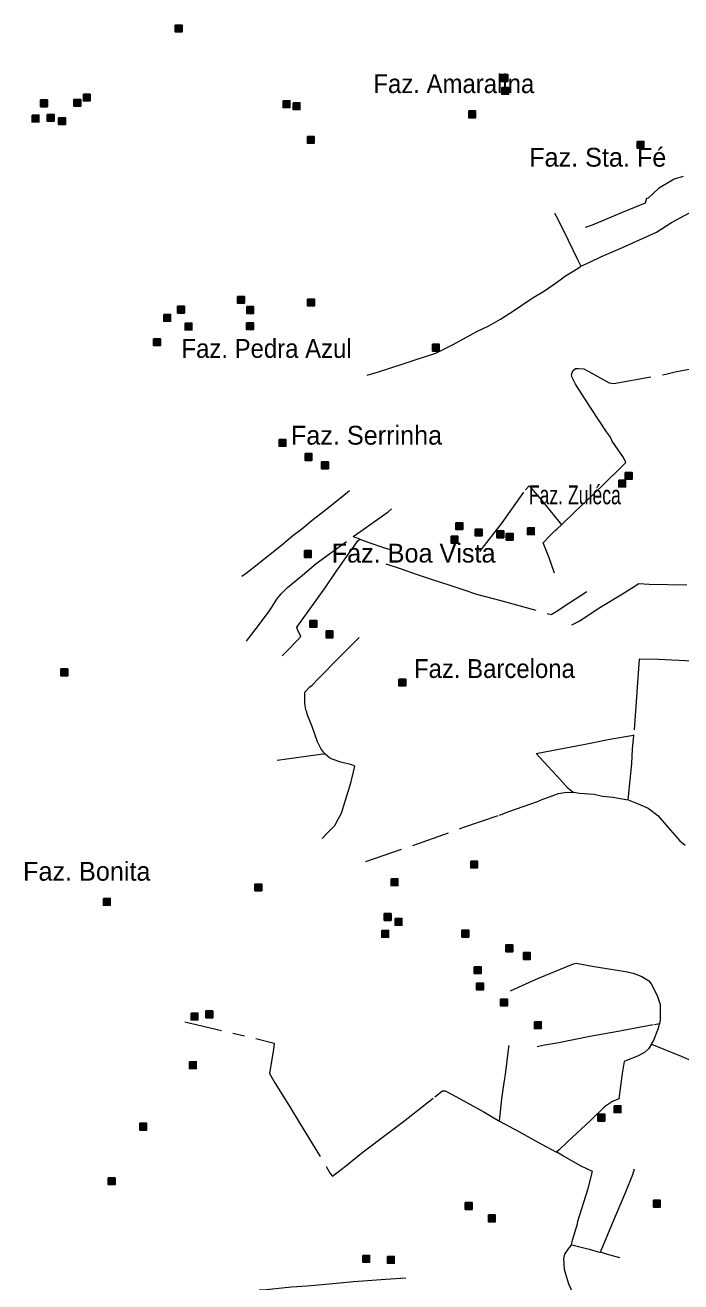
# Model space of a CAD drawing. Extents: x 393.5 to 446.9, y 8064.8 to 8120.4.
# Drawn here: x 399.42 to 404.99, y 8098.67 to 8109.36 of the extents above; entities that cross this region are included whole.
import ezdxf

# ---------------------------------------------------------------- set-up
doc = ezdxf.new("R2010")
doc.units = 0
doc.header["$LTSCALE"] = 0.064
doc.linetypes.add('DOT_DASHED', pattern=[7.7, 5, -1.2, 0.3, -1.2])
doc.layers.add('2', color=7, linetype='Continuous', lineweight=25)
doc.layers.add('22', color=7, linetype='DOT_DASHED', lineweight=13)
doc.layers.add('61', color=7, linetype='Continuous')

msp = doc.modelspace()

# ---------------------------------------------------------------- hatches: boundary and pattern name
at = {"layer": '2'}
for points in [[(400.692, 8109.3558), (400.75, 8109.3558), (400.75, 8109.2978), (400.692, 8109.2978)], [(403.4613, 8108.9358), (403.5193, 8108.9358), (403.5193, 8108.8778), (403.4613, 8108.8778)], [(399.9114, 8108.7688), (399.9694, 8108.7688), (399.9694, 8108.7108), (399.9114, 8108.7108)], [(403.4666, 8108.8256), (403.5246, 8108.8256), (403.5246, 8108.7676), (403.4666, 8108.7676)], [(399.5481, 8108.7203), (399.6061, 8108.7203), (399.6061, 8108.6623), (399.5481, 8108.6623)], [(399.832, 8108.7241), (399.89, 8108.7241), (399.89, 8108.6661), (399.832, 8108.6661)], [(401.6092, 8108.7122), (401.6672, 8108.7122), (401.6672, 8108.6542), (401.6092, 8108.6542)], [(401.6943, 8108.6962), (401.7523, 8108.6962), (401.7523, 8108.6382), (401.6943, 8108.6382)], [(403.1868, 8108.6266), (403.2448, 8108.6266), (403.2448, 8108.5686), (403.1868, 8108.5686)], [(399.4754, 8108.591), (399.5334, 8108.591), (399.5334, 8108.533), (399.4754, 8108.533)], [(399.6053, 8108.5969), (399.6633, 8108.5969), (399.6633, 8108.5389), (399.6053, 8108.5389)], [(399.7012, 8108.5686), (399.7592, 8108.5686), (399.7592, 8108.5106), (399.7012, 8108.5106)], [(401.8147, 8108.4095), (401.8727, 8108.4095), (401.8727, 8108.3515), (401.8147, 8108.3515)], [(404.6172, 8108.3674), (404.6752, 8108.3674), (404.6752, 8108.3094), (404.6172, 8108.3094)], [(401.2219, 8107.0492), (401.2799, 8107.0492), (401.2799, 8106.9912), (401.2219, 8106.9912)], [(401.8169, 8107.0259), (401.8749, 8107.0259), (401.8749, 8106.9679), (401.8169, 8106.9679)], [(400.712, 8106.9658), (400.77, 8106.9658), (400.77, 8106.9078), (400.712, 8106.9078)], [(401.2995, 8106.9627), (401.3575, 8106.9627), (401.3575, 8106.9047), (401.2995, 8106.9047)], [(400.5945, 8106.8956), (400.6525, 8106.8956), (400.6525, 8106.8376), (400.5945, 8106.8376)], [(400.7756, 8106.8219), (400.8336, 8106.8219), (400.8336, 8106.7639), (400.7756, 8106.7639)], [(401.2982, 8106.8258), (401.3562, 8106.8258), (401.3562, 8106.7678), (401.2982, 8106.7678)], [(400.5087, 8106.6894), (400.5667, 8106.6894), (400.5667, 8106.6314), (400.5087, 8106.6314)], [(402.8782, 8106.6418), (402.9362, 8106.6418), (402.9362, 8106.5838), (402.8782, 8106.5838)], [(401.5744, 8105.8325), (401.6324, 8105.8325), (401.6324, 8105.7745), (401.5744, 8105.7745)], [(401.7956, 8105.7133), (401.8536, 8105.7133), (401.8536, 8105.6553), (401.7956, 8105.6553)], [(401.9352, 8105.6414), (401.9932, 8105.6414), (401.9932, 8105.5834), (401.9352, 8105.5834)], [(404.5165, 8105.5526), (404.5745, 8105.5526), (404.5745, 8105.4946), (404.5165, 8105.4946)], [(404.4601, 8105.4881), (404.5181, 8105.4881), (404.5181, 8105.4301), (404.4601, 8105.4301)], [(403.0767, 8105.125), (403.1347, 8105.125), (403.1347, 8105.067), (403.0767, 8105.067)], [(403.0365, 8105.0101), (403.0945, 8105.0101), (403.0945, 8104.9521), (403.0365, 8104.9521)], [(403.2421, 8105.071), (403.3001, 8105.071), (403.3001, 8105.013), (403.2421, 8105.013)], [(403.4251, 8105.0555), (403.4831, 8105.0555), (403.4831, 8104.9975), (403.4251, 8104.9975)], [(403.5051, 8105.0347), (403.5631, 8105.0347), (403.5631, 8104.9767), (403.5051, 8104.9767)], [(403.6853, 8105.0819), (403.7433, 8105.0819), (403.7433, 8105.0239), (403.6853, 8105.0239)], [(401.7897, 8104.8878), (401.8477, 8104.8878), (401.8477, 8104.8298), (401.7897, 8104.8298)], [(401.8366, 8104.2946), (401.8946, 8104.2946), (401.8946, 8104.2366), (401.8366, 8104.2366)], [(401.9734, 8104.2048), (402.0314, 8104.2048), (402.0314, 8104.1468), (401.9734, 8104.1468)], [(399.7212, 8103.8813), (399.7792, 8103.8813), (399.7792, 8103.8233), (399.7212, 8103.8233)], [(402.5931, 8103.796), (402.6511, 8103.796), (402.6511, 8103.738), (402.5931, 8103.738)], [(403.2025, 8102.2483), (403.2605, 8102.2483), (403.2605, 8102.1903), (403.2025, 8102.1903)], [(401.3688, 8102.0531), (401.4268, 8102.0531), (401.4268, 8101.9951), (401.3688, 8101.9951)], [(402.5265, 8102.0984), (402.5845, 8102.0984), (402.5845, 8102.0404), (402.5265, 8102.0404)], [(400.0826, 8101.9302), (400.1406, 8101.9302), (400.1406, 8101.8722), (400.0826, 8101.8722)], [(402.4677, 8101.8018), (402.5257, 8101.8018), (402.5257, 8101.7438), (402.4677, 8101.7438)], [(402.5606, 8101.7609), (402.6186, 8101.7609), (402.6186, 8101.7029), (402.5606, 8101.7029)], [(402.4471, 8101.659), (402.5051, 8101.659), (402.5051, 8101.601), (402.4471, 8101.601)], [(403.1282, 8101.6599), (403.1862, 8101.6599), (403.1862, 8101.6019), (403.1282, 8101.6019)], [(403.5017, 8101.5346), (403.5597, 8101.5346), (403.5597, 8101.4766), (403.5017, 8101.4766)], [(403.6509, 8101.47), (403.7089, 8101.47), (403.7089, 8101.412), (403.6509, 8101.412)], [(403.2329, 8101.3493), (403.2909, 8101.3493), (403.2909, 8101.2913), (403.2329, 8101.2913)], [(403.2534, 8101.2111), (403.3114, 8101.2111), (403.3114, 8101.1531), (403.2534, 8101.1531)], [(403.4571, 8101.0749), (403.5151, 8101.0749), (403.5151, 8101.0169), (403.4571, 8101.0169)], [(400.8265, 8100.9553), (400.8845, 8100.9553), (400.8845, 8100.8973), (400.8265, 8100.8973)], [(400.9528, 8100.9735), (401.0108, 8100.9735), (401.0108, 8100.9155), (400.9528, 8100.9155)], [(403.7437, 8100.8819), (403.8017, 8100.8819), (403.8017, 8100.8239), (403.7437, 8100.8239)], [(400.8126, 8100.542), (400.8706, 8100.542), (400.8706, 8100.484), (400.8126, 8100.484)], [(404.284, 8100.0948), (404.342, 8100.0948), (404.342, 8100.0368), (404.284, 8100.0368)], [(404.4204, 8100.1671), (404.4784, 8100.1671), (404.4784, 8100.1091), (404.4204, 8100.1091)], [(400.3905, 8100.0189), (400.4485, 8100.0189), (400.4485, 8099.9609), (400.3905, 8099.9609)], [(400.1231, 8099.5547), (400.1811, 8099.5547), (400.1811, 8099.4967), (400.1231, 8099.4967)], [(403.1566, 8099.3446), (403.2146, 8099.3446), (403.2146, 8099.2866), (403.1566, 8099.2866)], [(404.755, 8099.3644), (404.813, 8099.3644), (404.813, 8099.3064), (404.755, 8099.3064)], [(403.3533, 8099.2391), (403.4113, 8099.2391), (403.4113, 8099.1811), (403.3533, 8099.1811)], [(402.2861, 8098.8958), (402.3441, 8098.8958), (402.3441, 8098.8378), (402.2861, 8098.8378)], [(402.4952, 8098.8869), (402.5532, 8098.8869), (402.5532, 8098.8289), (402.4952, 8098.8289)]]:
    msp.add_hatch(color=256, dxfattribs=at).paths.add_polyline_path(points)

# ---------------------------------------------------------------- linework, layer by layer
for points in [[(400.692, 8109.3558), (400.75, 8109.3558), (400.75, 8109.2978), (400.692, 8109.2978)], [(403.4613, 8108.9358), (403.5193, 8108.9358), (403.5193, 8108.8778), (403.4613, 8108.8778)], [(399.9114, 8108.7688), (399.9694, 8108.7688), (399.9694, 8108.7108), (399.9114, 8108.7108)], [(403.4666, 8108.8256), (403.5246, 8108.8256), (403.5246, 8108.7676), (403.4666, 8108.7676)], [(399.5481, 8108.7203), (399.6061, 8108.7203), (399.6061, 8108.6623), (399.5481, 8108.6623)], [(399.832, 8108.7241), (399.89, 8108.7241), (399.89, 8108.6661), (399.832, 8108.6661)], [(401.6092, 8108.7122), (401.6672, 8108.7122), (401.6672, 8108.6542), (401.6092, 8108.6542)], [(401.6943, 8108.6962), (401.7523, 8108.6962), (401.7523, 8108.6382), (401.6943, 8108.6382)], [(403.1868, 8108.6266), (403.2448, 8108.6266), (403.2448, 8108.5686), (403.1868, 8108.5686)], [(399.4754, 8108.591), (399.5334, 8108.591), (399.5334, 8108.533), (399.4754, 8108.533)], [(399.6053, 8108.5969), (399.6633, 8108.5969), (399.6633, 8108.5389), (399.6053, 8108.5389)], [(399.7012, 8108.5686), (399.7592, 8108.5686), (399.7592, 8108.5106), (399.7012, 8108.5106)], [(401.8147, 8108.4095), (401.8727, 8108.4095), (401.8727, 8108.3515), (401.8147, 8108.3515)], [(404.6172, 8108.3674), (404.6752, 8108.3674), (404.6752, 8108.3094), (404.6172, 8108.3094)], [(401.2219, 8107.0492), (401.2799, 8107.0492), (401.2799, 8106.9912), (401.2219, 8106.9912)], [(401.8169, 8107.0259), (401.8749, 8107.0259), (401.8749, 8106.9679), (401.8169, 8106.9679)], [(400.712, 8106.9658), (400.77, 8106.9658), (400.77, 8106.9078), (400.712, 8106.9078)], [(401.2995, 8106.9627), (401.3575, 8106.9627), (401.3575, 8106.9047), (401.2995, 8106.9047)], [(400.5945, 8106.8956), (400.6525, 8106.8956), (400.6525, 8106.8376), (400.5945, 8106.8376)], [(400.7756, 8106.8219), (400.8336, 8106.8219), (400.8336, 8106.7639), (400.7756, 8106.7639)], [(401.2982, 8106.8258), (401.3562, 8106.8258), (401.3562, 8106.7678), (401.2982, 8106.7678)], [(400.5087, 8106.6894), (400.5667, 8106.6894), (400.5667, 8106.6314), (400.5087, 8106.6314)], [(402.8782, 8106.6418), (402.9362, 8106.6418), (402.9362, 8106.5838), (402.8782, 8106.5838)], [(401.5744, 8105.8325), (401.6324, 8105.8325), (401.6324, 8105.7745), (401.5744, 8105.7745)], [(401.7956, 8105.7133), (401.8536, 8105.7133), (401.8536, 8105.6553), (401.7956, 8105.6553)], [(401.9352, 8105.6414), (401.9932, 8105.6414), (401.9932, 8105.5834), (401.9352, 8105.5834)], [(404.5165, 8105.5526), (404.5745, 8105.5526), (404.5745, 8105.4946), (404.5165, 8105.4946)], [(404.4601, 8105.4881), (404.5181, 8105.4881), (404.5181, 8105.4301), (404.4601, 8105.4301)], [(403.0767, 8105.125), (403.1347, 8105.125), (403.1347, 8105.067), (403.0767, 8105.067)], [(403.0365, 8105.0101), (403.0945, 8105.0101), (403.0945, 8104.9521), (403.0365, 8104.9521)], [(403.2421, 8105.071), (403.3001, 8105.071), (403.3001, 8105.013), (403.2421, 8105.013)], [(403.4251, 8105.0555), (403.4831, 8105.0555), (403.4831, 8104.9975), (403.4251, 8104.9975)], [(403.5051, 8105.0347), (403.5631, 8105.0347), (403.5631, 8104.9767), (403.5051, 8104.9767)], [(403.6853, 8105.0819), (403.7433, 8105.0819), (403.7433, 8105.0239), (403.6853, 8105.0239)], [(401.7897, 8104.8878), (401.8477, 8104.8878), (401.8477, 8104.8298), (401.7897, 8104.8298)], [(401.8366, 8104.2946), (401.8946, 8104.2946), (401.8946, 8104.2366), (401.8366, 8104.2366)], [(401.9734, 8104.2048), (402.0314, 8104.2048), (402.0314, 8104.1468), (401.9734, 8104.1468)], [(399.7212, 8103.8813), (399.7792, 8103.8813), (399.7792, 8103.8233), (399.7212, 8103.8233)], [(402.5931, 8103.796), (402.6511, 8103.796), (402.6511, 8103.738), (402.5931, 8103.738)], [(403.2025, 8102.2483), (403.2605, 8102.2483), (403.2605, 8102.1903), (403.2025, 8102.1903)], [(401.3688, 8102.0531), (401.4268, 8102.0531), (401.4268, 8101.9951), (401.3688, 8101.9951)], [(402.5265, 8102.0984), (402.5845, 8102.0984), (402.5845, 8102.0404), (402.5265, 8102.0404)], [(400.0826, 8101.9302), (400.1406, 8101.9302), (400.1406, 8101.8722), (400.0826, 8101.8722)], [(402.4677, 8101.8018), (402.5257, 8101.8018), (402.5257, 8101.7438), (402.4677, 8101.7438)], [(402.5606, 8101.7609), (402.6186, 8101.7609), (402.6186, 8101.7029), (402.5606, 8101.7029)], [(402.4471, 8101.659), (402.5051, 8101.659), (402.5051, 8101.601), (402.4471, 8101.601)], [(403.1282, 8101.6599), (403.1862, 8101.6599), (403.1862, 8101.6019), (403.1282, 8101.6019)], [(403.5017, 8101.5346), (403.5597, 8101.5346), (403.5597, 8101.4766), (403.5017, 8101.4766)], [(403.6509, 8101.47), (403.7089, 8101.47), (403.7089, 8101.412), (403.6509, 8101.412)], [(403.2329, 8101.3493), (403.2909, 8101.3493), (403.2909, 8101.2913), (403.2329, 8101.2913)], [(403.2534, 8101.2111), (403.3114, 8101.2111), (403.3114, 8101.1531), (403.2534, 8101.1531)], [(403.4571, 8101.0749), (403.5151, 8101.0749), (403.5151, 8101.0169), (403.4571, 8101.0169)], [(400.8265, 8100.9553), (400.8845, 8100.9553), (400.8845, 8100.8973), (400.8265, 8100.8973)], [(400.9528, 8100.9735), (401.0108, 8100.9735), (401.0108, 8100.9155), (400.9528, 8100.9155)], [(403.7437, 8100.8819), (403.8017, 8100.8819), (403.8017, 8100.8239), (403.7437, 8100.8239)], [(400.8126, 8100.542), (400.8706, 8100.542), (400.8706, 8100.484), (400.8126, 8100.484)], [(404.284, 8100.0948), (404.342, 8100.0948), (404.342, 8100.0368), (404.284, 8100.0368)], [(404.4204, 8100.1671), (404.4784, 8100.1671), (404.4784, 8100.1091), (404.4204, 8100.1091)], [(400.3905, 8100.0189), (400.4485, 8100.0189), (400.4485, 8099.9609), (400.3905, 8099.9609)], [(400.1231, 8099.5547), (400.1811, 8099.5547), (400.1811, 8099.4967), (400.1231, 8099.4967)], [(403.1566, 8099.3446), (403.2146, 8099.3446), (403.2146, 8099.2866), (403.1566, 8099.2866)], [(404.755, 8099.3644), (404.813, 8099.3644), (404.813, 8099.3064), (404.755, 8099.3064)], [(403.3533, 8099.2391), (403.4113, 8099.2391), (403.4113, 8099.1811), (403.3533, 8099.1811)], [(402.2861, 8098.8958), (402.3441, 8098.8958), (402.3441, 8098.8378), (402.2861, 8098.8378)], [(402.4952, 8098.8869), (402.5532, 8098.8869), (402.5532, 8098.8289), (402.4952, 8098.8289)]]:
    msp.add_lwpolyline(points, close=True, dxfattribs=at)
at = {"layer": '22'}
msp.add_line((404.139, 8107.3074), (404.1387, 8107.3081), dxfattribs=at)
for points in [[(405.0077, 8108.0697), (404.9322, 8108.0461), (404.7977, 8107.9658), (404.7095, 8107.8856), (404.697, 8107.8825), (404.6844, 8107.8432), (404.4688, 8107.7551), (404.2335, 8107.656), (404.1745, 8107.6357)], [(404.139, 8107.3074), (404.2146, 8107.3404), (404.3145, 8107.3897), (404.4926, 8107.4647), (404.7815, 8107.5959), (404.9089, 8107.6776), (405.1355, 8107.7987)], [(404.1387, 8107.3081), (404.1139, 8107.3608), (404.0337, 8107.5256), (403.9432, 8107.708), (403.918, 8107.7536)], [(402.3235, 8106.3785), (402.4195, 8106.4068), (402.6209, 8106.4744), (402.7468, 8106.5153), (402.9073, 8106.5672), (403.0537, 8106.6395), (403.2547, 8106.7517), (403.357, 8106.8004), (403.4561, 8106.857), (403.5757, 8106.9325), (403.7244, 8107.0331), (403.8298, 8107.0976), (403.9321, 8107.1683), (403.9746, 8107.1982), (403.9988, 8107.2183), (404.117, 8107.2885), (404.139, 8107.3074)], [(404.3893, 8105.8512), (404.3578, 8105.8982), (404.2273, 8106.0967), (404.0919, 8106.3017), (404.0635, 8106.3602), (404.0601, 8106.3835), (404.0702, 8106.4152), (404.0936, 8106.4353), (404.1186, 8106.4369), (404.1637, 8106.4336), (404.2071, 8106.4119), (404.3792, 8106.3134), (404.4193, 8106.3084), (404.8607, 8106.3883), (404.9392, 8106.4067), (405.1948, 8106.4551), (405.3451, 8106.4818)], [(403.9747, 8105.1076), (404.087, 8105.2164), (404.239, 8105.3599), (404.467, 8105.5825), (404.5205, 8105.6359), (404.5004, 8105.6793), (404.4036, 8105.8195), (404.3893, 8105.8512)], [(403.2809, 8104.8792), (403.4697, 8105.1227), (403.669, 8105.4049), (403.6996, 8105.4375), (403.8035, 8105.3173), (403.9502, 8105.1361), (403.9747, 8105.1076)], [(401.6918, 8105.0166), (401.7678, 8105.0744), (401.8547, 8105.1468), (401.956, 8105.2245), (402.1071, 8105.3456), (402.1723, 8105.3981)], [(402.2044, 8105.0073), (402.2985, 8105.0742), (402.5003, 8105.217), (402.5311, 8105.2441)], [(403.9199, 8105.058), (403.9339, 8105.0709), (403.9743, 8105.1072), (403.9747, 8105.1076)], [(401.2593, 8104.6694), (401.2955, 8104.6947), (401.3878, 8104.7706), (401.5941, 8104.9352), (401.6918, 8105.0166)], [(401.5558, 8104.4744), (401.5936, 8104.5208), (401.6461, 8104.5732), (401.7746, 8104.6799), (401.8886, 8104.7794), (402.2044, 8105.0073)], [(402.2605, 8104.9856), (402.2079, 8105.006), (402.2044, 8105.0073)], [(403.9134, 8104.6958), (403.8705, 8104.8258), (403.8181, 8104.9544), (403.8765, 8105.0145), (403.9199, 8105.058)], [(402.0871, 8104.7492), (402.1339, 8104.8152), (402.2128, 8104.9264), (402.241, 8104.9687), (402.2605, 8104.9856)], [(402.2605, 8104.9856), (402.3382, 8104.9574), (402.4692, 8104.9109), (402.5171, 8104.8983)], [(401.6011, 8103.9937), (401.641, 8104.0332), (401.7269, 8104.1247), (401.7593, 8104.1571), (401.7297, 8104.2176), (401.7241, 8104.2359), (401.808, 8104.3513), (401.9009, 8104.4808), (401.9657, 8104.5723), (402.0594, 8104.7104), (402.0871, 8104.7492)], [(402.4822, 8104.7748), (402.6126, 8104.732), (402.739, 8104.6872), (402.8837, 8104.6404), (403.0182, 8104.5956), (403.1527, 8104.5528), (403.2526, 8104.5162), (403.4478, 8104.4657), (403.8525, 8104.3536), (403.8872, 8104.3455), (403.9279, 8104.3699), (404.0461, 8104.4473), (404.1888, 8104.541)], [(404.0627, 8104.2571), (404.1245, 8104.2882), (404.3013, 8104.4034), (404.5066, 8104.5294), (404.6327, 8104.6093), (404.7203, 8104.6016), (405.1515, 8104.594), (405.2069, 8104.5955)], [(401.297, 8104.1182), (401.3241, 8104.1507), (401.3911, 8104.2393), (401.4997, 8104.384), (401.5558, 8104.4744)], [(401.8547, 8103.7442), (401.9075, 8103.7986), (402.0847, 8103.9778), (402.254, 8104.1493)], [(405.084, 8103.947), (404.7985, 8103.9624), (404.6355, 8103.9655), (404.6151, 8103.6837), (404.5882, 8103.3201)], [(401.8027, 8103.5346), (401.7936, 8103.5909), (401.7922, 8103.6838), (401.8372, 8103.7303), (401.8547, 8103.7442)], [(401.9638, 8103.1608), (401.9286, 8103.2044), (401.9004, 8103.2622), (401.8578, 8103.3831), (401.8145, 8103.4958), (401.8103, 8103.5183), (401.8027, 8103.5346)], [(404.0698, 8102.8337), (404.0308, 8102.8658), (403.9625, 8102.9415), (403.7586, 8103.1638), (403.9508, 8103.2007), (404.1614, 8103.2407), (404.3844, 8103.2852), (404.5859, 8103.3197), (404.5882, 8103.3201)], [(404.5417, 8102.7675), (404.5713, 8103.079), (404.5775, 8103.1988), (404.5877, 8103.3144), (404.5882, 8103.32), (404.5882, 8103.3201)], [(401.5582, 8103.106), (401.6417, 8103.1164), (401.9258, 8103.1566), (401.9612, 8103.1605), (401.9638, 8103.1608)], [(402.1933, 8102.9482), (402.2186, 8103.0558), (402.1932, 8103.0657), (402.0989, 8103.0882), (402.0256, 8103.1149), (402.0041, 8103.1269), (401.9638, 8103.1608)], [(402.1168, 8102.6918), (402.1244, 8102.722), (402.175, 8102.8846), (402.1876, 8102.9254), (402.1933, 8102.9482)], [(402.313, 8102.2449), (402.7121, 8102.3818), (403.1346, 8102.5324), (403.4464, 8102.639), (403.5264, 8102.6697), (403.7139, 8102.7342), (403.7785, 8102.7588), (403.802, 8102.7699), (403.9483, 8102.8229), (404.0006, 8102.8306), (404.0698, 8102.8337), (404.0757, 8102.8329)], [(404.0757, 8102.8329), (404.1282, 8102.826), (404.2527, 8102.8183), (404.3234, 8102.7999), (404.4126, 8102.7906), (404.4568, 8102.7841), (404.5417, 8102.7675)], [(404.5417, 8102.7675), (404.6246, 8102.7354), (404.7112, 8102.6982), (404.7925, 8102.6356), (404.8817, 8102.5344), (404.981, 8102.4212), (405.025, 8102.3826)], [(401.9413, 8102.4404), (401.9794, 8102.4812), (402.0484, 8102.5502), (402.078, 8102.6051), (402.102, 8102.6501), (402.1104, 8102.6712), (402.1168, 8102.6918)], [(403.541, 8101.145), (403.6706, 8101.2052), (403.7799, 8101.2538), (404.0756, 8101.3732), (404.0999, 8101.3813), (404.2357, 8101.355), (404.5167, 8101.3104), (404.5834, 8101.2961), (404.6581, 8101.2659), (404.7153, 8101.231), (404.7375, 8101.2056), (404.7868, 8101.104), (404.8122, 8101.0278), (404.8114, 8100.8945), (404.8061, 8100.8665), (404.8059, 8100.8656)], [(400.7742, 8100.8826), (401.5317, 8100.7011), (401.5281, 8100.6456), (401.5004, 8100.4969), (401.4931, 8100.4429), (401.5398, 8100.3627), (401.6573, 8100.1731), (401.7558, 8100.0083), (402.0098, 8099.5926), (402.0273, 8099.5693), (402.1382, 8099.6553), (402.2885, 8099.7749), (402.4965, 8099.9325), (402.6307, 8100.0345), (402.8985, 8100.243), (402.9642, 8100.2955), (402.9846, 8100.294), (403.0766, 8100.2459), (403.3079, 8100.1177), (403.4478, 8100.0372)], [(403.9516, 8100.7057), (404.2153, 8100.758), (404.4393, 8100.7993), (404.7657, 8100.8597), (404.8061, 8100.8665)], [(404.7393, 8100.69), (404.7561, 8100.7189), (404.7977, 8100.8266), (404.8059, 8100.8656)], [(403.4931, 8100.4001), (403.4971, 8100.4325), (403.5266, 8100.666), (403.5295, 8100.6806)], [(403.7674, 8100.6707), (403.815, 8100.6834), (403.9516, 8100.7057)], [(404.7393, 8100.69), (404.7128, 8100.6517), (404.6792, 8100.6211), (404.6208, 8100.5905), (404.542, 8100.5569), (404.507, 8100.5438), (404.4909, 8100.4432), (404.4603, 8100.2272), (404.4078, 8100.2039), (404.3407, 8100.1587), (404.2195, 8100.042), (404.0254, 8099.8598), (403.9532, 8099.7926), (403.9322, 8099.7735)], [(404.7393, 8100.69), (404.9904, 8100.5891), (405.2017, 8100.4986), (405.3352, 8100.4383), (405.3828, 8100.4319), (405.4305, 8100.4351), (405.4988, 8100.4605), (405.5814, 8100.4811), (405.6217, 8100.4929)], [(403.4478, 8100.0372), (403.4684, 8100.2251), (403.4844, 8100.3446), (403.4931, 8100.4001)], [(403.4478, 8100.0372), (403.6124, 8099.9487), (403.7802, 8099.8539), (403.8474, 8099.8175), (403.9322, 8099.7735)], [(404.1138, 8099.1871), (404.2017, 8099.4653), (404.2383, 8099.6074), (404.1427, 8099.6553), (403.9924, 8099.7384), (403.9338, 8099.7725), (403.9322, 8099.7735)], [(404.3089, 8098.9221), (404.3103, 8098.9392), (404.3249, 8098.9717), (404.4019, 8099.1552), (404.5208, 8099.4362), (404.5815, 8099.584), (404.5946, 8099.6306)], [(404.0586, 8098.9864), (404.0668, 8099.025), (404.1106, 8099.1635), (404.1138, 8099.1871)], [(404.0701, 8098.5784), (404.0368, 8098.651), (404.0105, 8098.737), (403.9995, 8098.775), (403.9951, 8098.8698), (404.0039, 8098.9048), (404.0331, 8098.9515), (404.0433, 8098.9617), (404.0608, 8098.985), (404.0615, 8098.9848)], [(404.0615, 8098.9848), (404.2082, 8098.9471), (404.287, 8098.925), (404.307, 8098.9224), (404.3089, 8098.9221)], [(404.4694, 8098.874), (404.3556, 8098.906), (404.3307, 8098.9133), (404.3089, 8098.9221)], [(402.6519, 8098.7019), (402.4829, 8098.6906), (402.2079, 8098.6703), (402.032, 8098.6546), (401.8134, 8098.6343), (401.6804, 8098.6253), (401.4392, 8098.6005), (401.4047, 8098.5984)]]:
    msp.add_lwpolyline(points, dxfattribs=at)

# ---------------------------------------------------------------- texts
at = {"layer": '61'}
for s, width, p in [('Faz. Amaralina', 0.95, (402.3761, 8108.778)), ('Faz. Pedra Azul', 0.95, (400.7453, 8106.5266)), ('Faz. Zuléca', 0.7, (403.6962, 8105.2817)), ('Faz. Barcelona', 0.95, (402.7208, 8103.805))]:
    msp.add_text(s, height=0.16, dxfattribs=dict(at, width=width)).set_placement(p)
for s, p in [('Faz. Sta. Fé', (403.6995, 8108.1525)), ('Faz. Serrinha', (401.6755, 8105.7889)), ('Faz. Boa Vista', (402.0222, 8104.7864)), ('Faz. Bonita', (399.3995, 8102.0814))]:
    msp.add_text(s, height=0.16, dxfattribs=at).set_placement(p)

doc.saveas('drawing.dxf')
